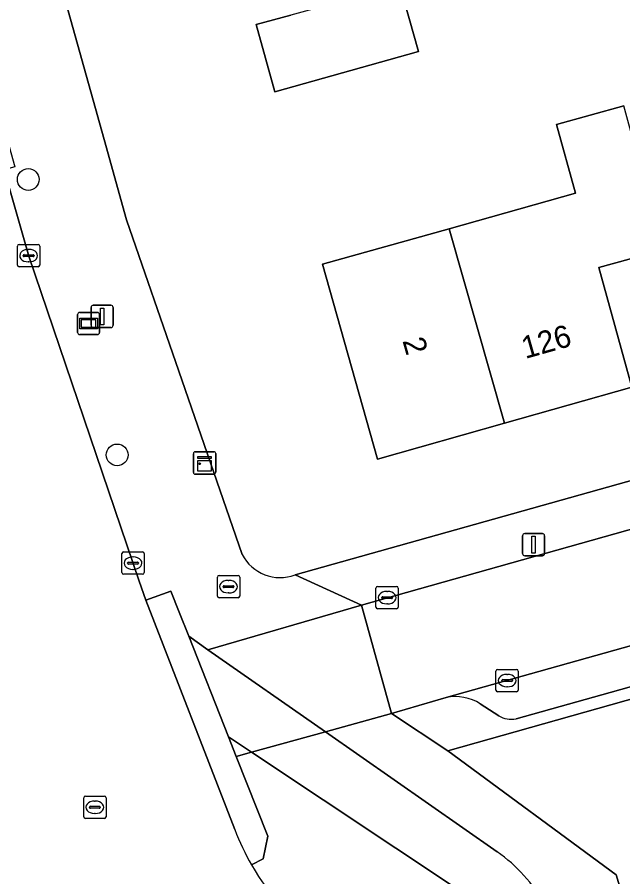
# Model space of a CAD drawing. Extents: x 159626 to 160723, y 388173 to 389416.
# Drawn here: x 160026.77 to 160053.93, y 388288.84 to 388327.38 of the extents above; entities that cross this region are included whole.
import ezdxf

# ---------------------------------------------------------------- set-up
doc = ezdxf.new("R2010")
doc.units = 0
for name, color, linetype in [('IMGEO_Boom', 7, 'Continuous'), ('IMGEO_Brandkraan', 7, 'Continuous'), ('IMGEO_Erf', 7, 'Continuous'), ('IMGEO_Fietspad_open', 7, 'Continuous'), ('IMGEO_Groenvoorziening', 7, 'Continuous'), ('IMGEO_Informatiebord', 7, 'Continuous'), ('IMGEO_Kast', 7, 'Continuous'), ('IMGEO_Kolk', 7, 'Continuous'), ('IMGEO_Lichtmast', 7, 'Continuous'), ('IMGEO_Muur', 7, 'Continuous'), ('IMGEO_Pand', 7, 'Continuous'), ('IMGEO_Pand_nummerreeks', 7, 'Continuous'), ('IMGEO_Parkeervlak_open', 7, 'Continuous'), ('IMGEO_Rijbaan_lokaal_gesloten', 7, 'Continuous'), ('IMGEO_Rijbaan_lokaal_open', 7, 'Continuous'), ('IMGEO_Rioolput', 7, 'Continuous'), ('IMGEO_Verkeerseiland_open', 7, 'Continuous'), ('IMGEO_Voetpad_open', 7, 'Continuous')]:
    doc.layers.add(name, color=color, linetype=linetype)

msp = doc.modelspace()

# ---------------------------------------------------------------- linework, layer by layer
at = {"layer": 'IMGEO_Boom'}
for centre in [(160027.263, 388320.109), (160031.247, 388307.757)]:
    msp.add_circle(centre, 0.489, dxfattribs=at)
at = {"layer": 'IMGEO_Brandkraan'}
for p, q in [((160035.743, 388301.426), (160035.743, 388302.278)), ((160035.818, 388302.352), (160036.67, 388302.352)), ((160036.744, 388302.278), (160036.744, 388301.426)), ((160036.002, 388301.846), (160036.002, 388301.858)), ((160036.045, 388301.895), (160036.443, 388301.895)), ((160036.231, 388302.132), (160036.256, 388302.132)), ((160036.486, 388301.858), (160036.486, 388301.846)), ((160036.44, 388301.809), (160036.042, 388301.809)), ((160036.254, 388301.572), (160036.229, 388301.572)), ((160036.67, 388301.352), (160035.818, 388301.352))]:
    msp.add_line(p, q, dxfattribs=at)
for points in [[(160035.743, 388301.426), (160035.743, 388302.278)], [(160035.818, 388302.352), (160036.67, 388302.352)], [(160036.744, 388302.278), (160036.744, 388301.426)], [(160036.67, 388301.352), (160035.818, 388301.352)]]:
    msp.add_lwpolyline(points, dxfattribs=at)
for centre, radius, start, end in [((160035.82, 388302.276), 0.0765, 91.552, 178.448), ((160035.82, 388302.276), 0.0765, 91.552, 178.448), ((160036.668, 388302.276), 0.0765, 1.552, 88.448), ((160036.668, 388302.276), 0.0765, 1.552, 88.448), ((160036.042, 388301.855), 0.0403, 85.8775, 175.7526), ((160036.039, 388301.845), 0.0366, 178.938, 274.7102), ((160036.443, 388301.852), 0.043, 264.8664, 352.4533), ((160036.447, 388301.857), 0.0386, 1.7309, 96.639), ((160035.82, 388301.428), 0.0765, 181.552, 268.448), ((160035.82, 388301.428), 0.0765, 181.552, 268.448), ((160036.668, 388301.428), 0.0765, 271.552, 358.448), ((160036.668, 388301.428), 0.0765, 271.552, 358.448)]:
    msp.add_arc(centre, radius, start, end, dxfattribs=at)
for centre, major_axis, ratio, start_param, end_param in [((160036.23, 388301.852), (-0.387, 0.002), 0.722429, 4.712389, 7.853982), ((160036.255, 388301.852), (-0.39, 0.002), 0.717154, 1.570796, 4.712389)]:
    msp.add_ellipse(centre, major_axis=major_axis, ratio=ratio, start_param=start_param, end_param=end_param, dxfattribs=at)
at = {"layer": 'IMGEO_Erf'}
for points in [[(160065.737, 388357.839), (160068.821, 388358.703), (160067.258, 388364.278), (160065.672, 388369.937), (160062.589, 388369.073), (160061.749, 388372.073), (160060.886, 388375.152), (160063.97, 388376.017), (160062.406, 388381.596), (160060.811, 388387.289), (160057.729, 388386.426), (160056.908, 388389.358), (160055.27, 388395.203), (160052.188, 388394.339), (160051.374, 388397.24), (160039.731, 388394.019), (160038.102, 388399.961), (160014.614, 388386.787), (160012.651, 388386.243), (160030.665, 388321.896), (160031.671, 388318.304), (160034.012, 388311.518), (160036.849, 388303.296)], [(160043.934, 388328.825), (160044.769, 388325.844), (160038.317, 388324.038), (160037.477, 388327.05), (160039.034, 388327.478)], [(160055.733, 388316.955), (160052.856, 388316.157), (160054.33, 388310.792), (160048.625, 388309.176), (160042.922, 388307.561), (160040.457, 388316.304), (160046.135, 388317.896), (160051.813, 388319.487), (160050.949, 388322.566), (160053.969, 388323.413)], [(160039.23, 388302.377), (160091.966, 388317.174)]]:
    msp.add_lwpolyline(points, dxfattribs=at)
msp.add_arc((160038.563, 388304.192), 1.934, 207.5977, 290.1919, dxfattribs=at)
at = {"layer": 'IMGEO_Fietspad_open'}
msp.add_lwpolyline([(160035.321, 388299.02), (160034.457, 388299.624), (160036.245, 388295.111), (160037.282, 388294.423), (160040.586, 388295.343)], close=True, dxfattribs=at)
for points in [[(160040.586, 388295.343), (160037.282, 388294.423), (160046.969, 388287.994)], [(160048.297, 388289.956), (160040.586, 388295.343)]]:
    msp.add_lwpolyline(points, dxfattribs=at)
msp.add_arc((160044.428, 388284.351), 6.811, 28.4759, 55.3857, dxfattribs=at)
at = {"layer": 'IMGEO_Groenvoorziening'}
msp.add_lwpolyline([(160111.162, 388314.606), (160094.986, 388310.154), (160094.139, 388309.551), (160093.281, 388307.812), (160046.081, 388294.496), (160053.63, 388288.927), (160054.524, 388285.955)], dxfattribs=at)
at = {"layer": 'IMGEO_Informatiebord'}
for p, q in [((160029.474, 388313.25), (160029.474, 388314.05)), ((160029.474, 388314.05), (160029.474, 388313.25)), ((160029.574, 388314.15), (160030.364, 388314.15)), ((160030.364, 388314.15), (160029.574, 388314.15)), ((160030.464, 388314.05), (160030.464, 388313.25)), ((160030.464, 388313.25), (160030.464, 388314.05)), ((160030.364, 388313.15), (160029.574, 388313.15)), ((160029.574, 388313.15), (160030.364, 388313.15))]:
    msp.add_line(p, q, dxfattribs=at)
for points in [[(160029.575, 388313.882), (160030.363, 388313.882), (160030.363, 388313.418), (160029.575, 388313.418), (160029.575, 388313.882)], [(160029.64, 388313.817), (160029.64, 388313.483), (160030.298, 388313.483), (160030.298, 388313.817), (160029.64, 388313.817)]]:
    msp.add_lwpolyline(points, dxfattribs=at)
for centre, start, end in [((160029.574, 388314.05), 90, 180), ((160029.574, 388314.05), 90, 180), ((160030.364, 388314.05), 0, 90), ((160030.364, 388314.05), 360, 90), ((160029.574, 388313.25), 180, 270), ((160029.574, 388313.25), 180, 270), ((160030.364, 388313.25), 270, 0), ((160030.364, 388313.25), 270, 0)]:
    msp.add_arc(centre, 0.1, start, end, dxfattribs=at)
at = {"layer": 'IMGEO_Kast'}
for p, q in [((160034.67, 388306.972), (160034.67, 388307.813)), ((160034.67, 388307.813), (160034.67, 388306.972)), ((160034.745, 388307.897), (160035.586, 388307.897)), ((160035.586, 388307.897), (160034.745, 388307.897)), ((160035.67, 388307.822), (160035.67, 388306.981)), ((160035.67, 388306.981), (160035.67, 388307.822)), ((160035.595, 388306.897), (160034.754, 388306.897)), ((160034.754, 388306.897), (160035.595, 388306.897))]:
    msp.add_line(p, q, dxfattribs=at)
for points in [[(160034.865, 388307.687), (160035.465, 388307.687), (160035.465, 388307.602), (160034.865, 388307.602), (160034.865, 388307.687)], [(160034.865, 388307.512), (160035.465, 388307.512), (160035.465, 388307.023), (160034.865, 388307.023), (160034.865, 388307.512)]]:
    msp.add_lwpolyline(points, dxfattribs=at)
msp.add_circle((160034.949, 388307.361), 0.0377, dxfattribs=at)
for centre, start, end in [((160034.748, 388307.819), 92.4484, 184.2845), ((160034.748, 388307.819), 92.4484, 184.2845), ((160035.592, 388307.819), 2.4484, 94.2845), ((160035.592, 388307.819), 2.4484, 94.2845), ((160034.748, 388306.975), 182.4484, 274.2845), ((160034.748, 388306.975), 182.4484, 274.2845), ((160035.592, 388306.975), 272.4484, 4.2845), ((160035.592, 388306.975), 272.4484, 4.2845)]:
    msp.add_arc(centre, 0.0779, start, end, dxfattribs=at)
at = {"layer": 'IMGEO_Kolk'}
for p, q in [((160026.779, 388316.267), (160026.779, 388317.119)), ((160026.854, 388317.193), (160027.706, 388317.193)), ((160027.267, 388316.973), (160027.292, 388316.973)), ((160027.78, 388317.119), (160027.78, 388316.267)), ((160027.038, 388316.687), (160027.038, 388316.699)), ((160027.476, 388316.65), (160027.078, 388316.65)), ((160027.081, 388316.736), (160027.479, 388316.736)), ((160027.522, 388316.699), (160027.522, 388316.687)), ((160027.706, 388316.193), (160026.854, 388316.193)), ((160027.29, 388316.413), (160027.265, 388316.413)), ((160031.535, 388303.406), (160032.387, 388303.406)), ((160031.46, 388302.48), (160031.46, 388303.332)), ((160031.948, 388303.186), (160031.973, 388303.186)), ((160032.461, 388303.332), (160032.461, 388302.48)), ((160031.719, 388302.9), (160031.719, 388302.912)), ((160032.157, 388302.863), (160031.759, 388302.863)), ((160031.762, 388302.949), (160032.16, 388302.949)), ((160031.971, 388302.626), (160031.946, 388302.626)), ((160032.203, 388302.912), (160032.203, 388302.9)), ((160032.387, 388302.406), (160031.535, 388302.406)), ((160042.932, 388301.859), (160043.784, 388301.859)), ((160042.857, 388300.933), (160042.857, 388301.785)), ((160043.345, 388301.639), (160043.37, 388301.639)), ((160043.858, 388301.785), (160043.858, 388300.933)), ((160043.116, 388301.353), (160043.116, 388301.365)), ((160043.554, 388301.316), (160043.156, 388301.316)), ((160043.159, 388301.402), (160043.557, 388301.402)), ((160043.368, 388301.079), (160043.343, 388301.079)), ((160043.6, 388301.365), (160043.6, 388301.353)), ((160043.784, 388300.859), (160042.932, 388300.859)), ((160048.238, 388297.214), (160048.238, 388298.066)), ((160048.313, 388298.14), (160049.165, 388298.14)), ((160049.239, 388298.066), (160049.239, 388297.214)), ((160048.497, 388297.634), (160048.497, 388297.646)), ((160048.54, 388297.683), (160048.938, 388297.683)), ((160048.726, 388297.92), (160048.751, 388297.92)), ((160048.981, 388297.646), (160048.981, 388297.634)), ((160048.935, 388297.597), (160048.537, 388297.597)), ((160048.749, 388297.36), (160048.724, 388297.36)), ((160049.165, 388297.14), (160048.313, 388297.14))]:
    msp.add_line(p, q, dxfattribs=at)
for points in [[(160026.779, 388316.267), (160026.779, 388317.119)], [(160026.854, 388317.193), (160027.706, 388317.193)], [(160027.78, 388317.119), (160027.78, 388316.267)], [(160027.706, 388316.193), (160026.854, 388316.193)], [(160031.535, 388303.406), (160032.387, 388303.406)], [(160031.46, 388302.48), (160031.46, 388303.332)], [(160032.461, 388303.332), (160032.461, 388302.48)], [(160032.387, 388302.406), (160031.535, 388302.406)], [(160042.932, 388301.859), (160043.784, 388301.859)], [(160042.857, 388300.933), (160042.857, 388301.785)], [(160043.858, 388301.785), (160043.858, 388300.933)], [(160043.784, 388300.859), (160042.932, 388300.859)], [(160048.238, 388297.214), (160048.238, 388298.066)], [(160048.313, 388298.14), (160049.165, 388298.14)], [(160049.239, 388298.066), (160049.239, 388297.214)], [(160049.165, 388297.14), (160048.313, 388297.14)]]:
    msp.add_lwpolyline(points, dxfattribs=at)
for centre, radius, start, end in [((160026.856, 388317.117), 0.0765, 91.552, 178.448), ((160026.856, 388317.117), 0.0765, 91.552, 178.448), ((160027.704, 388317.117), 0.0765, 1.552, 88.448), ((160027.704, 388317.117), 0.0765, 1.552, 88.448), ((160027.078, 388316.696), 0.0403, 85.8775, 175.7526), ((160027.075, 388316.686), 0.0366, 178.938, 274.7102), ((160027.479, 388316.693), 0.043, 264.8664, 352.4533), ((160027.483, 388316.698), 0.0386, 1.7309, 96.639), ((160026.856, 388316.269), 0.0765, 181.552, 268.448), ((160026.856, 388316.269), 0.0765, 181.552, 268.448), ((160027.704, 388316.269), 0.0765, 271.552, 358.448), ((160027.704, 388316.269), 0.0765, 271.552, 358.448), ((160031.537, 388303.33), 0.0765, 91.552, 178.448), ((160031.537, 388303.33), 0.0765, 91.552, 178.448), ((160032.385, 388303.33), 0.0765, 1.552, 88.448), ((160032.385, 388303.33), 0.0765, 1.552, 88.448), ((160031.759, 388302.909), 0.0403, 85.8775, 175.7526), ((160031.756, 388302.899), 0.0366, 178.938, 274.7102), ((160032.16, 388302.906), 0.043, 264.8664, 352.4533), ((160032.164, 388302.911), 0.0386, 1.7309, 96.639), ((160031.537, 388302.482), 0.0765, 181.552, 268.448), ((160031.537, 388302.482), 0.0765, 181.552, 268.448), ((160032.385, 388302.482), 0.0765, 271.552, 358.448), ((160032.385, 388302.482), 0.0765, 271.552, 358.448), ((160042.934, 388301.783), 0.0765, 91.552, 178.448), ((160042.934, 388301.783), 0.0765, 91.552, 178.448), ((160043.782, 388301.783), 0.0765, 1.552, 88.448), ((160043.782, 388301.783), 0.0765, 1.552, 88.448), ((160043.156, 388301.362), 0.0403, 85.8775, 175.7526), ((160043.153, 388301.352), 0.0366, 178.938, 274.7102), ((160043.557, 388301.359), 0.043, 264.8664, 352.4533), ((160043.561, 388301.364), 0.0386, 1.7309, 96.639), ((160042.934, 388300.935), 0.0765, 181.552, 268.448), ((160042.934, 388300.935), 0.0765, 181.552, 268.448), ((160043.782, 388300.935), 0.0765, 271.552, 358.448), ((160043.782, 388300.935), 0.0765, 271.552, 358.448), ((160048.315, 388298.064), 0.0765, 91.552, 178.448), ((160048.315, 388298.064), 0.0765, 91.552, 178.448), ((160049.163, 388298.064), 0.0765, 1.552, 88.448), ((160049.163, 388298.064), 0.0765, 1.552, 88.448), ((160048.537, 388297.643), 0.0403, 85.8775, 175.7526), ((160048.534, 388297.633), 0.0366, 178.938, 274.7102), ((160048.938, 388297.64), 0.043, 264.8664, 352.4533), ((160048.942, 388297.645), 0.0386, 1.7309, 96.639), ((160048.315, 388297.216), 0.0765, 181.552, 268.448), ((160048.315, 388297.216), 0.0765, 181.552, 268.448), ((160049.163, 388297.216), 0.0765, 271.552, 358.448), ((160049.163, 388297.216), 0.0765, 271.552, 358.448)]:
    msp.add_arc(centre, radius, start, end, dxfattribs=at)
for centre, major_axis, ratio, start_param, end_param in [((160027.266, 388316.693), (-0.387, 0.002), 0.722429, 4.712389, 7.853982), ((160027.291, 388316.693), (-0.39, 0.002), 0.717154, 1.570796, 4.712389), ((160031.947, 388302.906), (-0.387, 0.002), 0.722429, 4.712389, 7.853982), ((160031.972, 388302.906), (-0.39, 0.002), 0.717154, 1.570796, 4.712389), ((160043.344, 388301.359), (-0.387, 0.002), 0.722429, 4.712389, 7.853982), ((160043.369, 388301.359), (-0.39, 0.002), 0.717154, 1.570796, 4.712389), ((160048.725, 388297.64), (-0.387, 0.002), 0.722429, 4.712389, 7.853982), ((160048.75, 388297.64), (-0.39, 0.002), 0.717154, 1.570796, 4.712389)]:
    msp.add_ellipse(centre, major_axis=major_axis, ratio=ratio, start_param=start_param, end_param=end_param, dxfattribs=at)
at = {"layer": 'IMGEO_Lichtmast'}
for p, q in [((160030.08, 388313.568), (160030.08, 388314.368)), ((160030.08, 388314.368), (160030.08, 388313.568)), ((160030.18, 388314.468), (160030.97, 388314.468)), ((160030.97, 388314.468), (160030.18, 388314.468)), ((160031.07, 388314.368), (160031.07, 388313.568)), ((160031.07, 388313.568), (160031.07, 388314.368)), ((160030.97, 388313.468), (160030.18, 388313.468)), ((160030.18, 388313.468), (160030.97, 388313.468)), ((160049.531, 388304.233), (160050.321, 388304.233)), ((160050.321, 388304.233), (160049.531, 388304.233)), ((160049.431, 388303.333), (160049.431, 388304.133)), ((160049.431, 388304.133), (160049.431, 388303.333)), ((160050.421, 388304.133), (160050.421, 388303.333)), ((160050.421, 388303.333), (160050.421, 388304.133)), ((160050.321, 388303.233), (160049.531, 388303.233)), ((160049.531, 388303.233), (160050.321, 388303.233))]:
    msp.add_line(p, q, dxfattribs=at)
for points in [[(160030.5, 388314.343), (160030.65, 388314.343), (160030.65, 388313.593), (160030.5, 388313.593), (160030.5, 388314.343)], [(160049.851, 388304.108), (160050.001, 388304.108), (160050.001, 388303.358), (160049.851, 388303.358), (160049.851, 388304.108)]]:
    msp.add_lwpolyline(points, dxfattribs=at)
for centre, start, end in [((160030.18, 388314.368), 90, 180), ((160030.18, 388314.368), 90, 180), ((160030.97, 388314.368), 0, 90), ((160030.97, 388314.368), 360, 90), ((160030.18, 388313.568), 180, 270), ((160030.18, 388313.568), 180, 270), ((160030.97, 388313.568), 270, 0), ((160030.97, 388313.568), 270, 0), ((160049.531, 388304.133), 90, 180), ((160049.531, 388304.133), 90, 180), ((160050.321, 388304.133), 0, 90), ((160050.321, 388304.133), 360, 90), ((160049.531, 388303.333), 180, 270), ((160049.531, 388303.333), 180, 270), ((160050.321, 388303.333), 270, 0), ((160050.321, 388303.333), 270, 0)]:
    msp.add_arc(centre, 0.1, start, end, dxfattribs=at)
at = {"layer": 'IMGEO_Muur'}
msp.add_lwpolyline([(160030.665, 388321.896), (160031.671, 388318.304), (160034.012, 388311.518)], dxfattribs=at)
at = {"layer": 'IMGEO_Pand'}
for points in [[(160043.934, 388328.825), (160039.034, 388327.478), (160037.477, 388327.05), (160038.317, 388324.038), (160044.769, 388325.844)], [(160048.625, 388309.176), (160054.33, 388310.792), (160052.856, 388316.157), (160055.733, 388316.955), (160053.969, 388323.413), (160050.949, 388322.566), (160051.813, 388319.487), (160046.135, 388317.896)], [(160048.625, 388309.176), (160046.135, 388317.896), (160040.457, 388316.304), (160042.922, 388307.561)]]:
    msp.add_lwpolyline(points, close=True, dxfattribs=at)
at = {"layer": 'IMGEO_Parkeervlak_open'}
for points in [[(160094.7, 388310.535), (160046.003, 388296.881)], [(160049.138, 388295.93), (160092.571, 388308.096)], [(160047.537, 388296.598), (160048.365, 388296.063)]]:
    msp.add_lwpolyline(points, dxfattribs=at)
for centre, radius, start, end in [((160046.416, 388294.819), 2.103, 57.7817, 101.3129), ((160048.918, 388296.963), 1.056, 238.4321, 282.0428)]:
    msp.add_arc(centre, radius, start, end, dxfattribs=at)
at = {"layer": 'IMGEO_Rijbaan_lokaal_gesloten'}
for points in [[(160032.543, 388301.251), (160032.232, 388302.091), (160027.287, 388316.662), (160026.183, 388320.536), (160019.347, 388319.41), (160020.694, 388314.057), (160023.709, 388300.3), (160024.04, 388298.788), (160024.077, 388298.593), (160026.043, 388289.19), (160026.077, 388288.953)], [(160036.528, 388290.956), (160032.543, 388301.251)]]:
    msp.add_lwpolyline(points, dxfattribs=at)
for centre, radius, start, end in [((160046.842, 388294.888), 11.038, 200.8688, 209.9821), ((160046.909, 388294.911), 11.107, 209.9125, 258.5931)]:
    msp.add_arc(centre, radius, start, end, dxfattribs=at)
at = {"layer": 'IMGEO_Rijbaan_lokaal_open'}
msp.add_lwpolyline([(160079.586, 388311.525), (160073.017, 388309.68), (160062.717, 388306.786), (160056.177, 388304.949), (160042.215, 388301.025), (160043.548, 388296.168), (160046.003, 388296.881), (160094.7, 388310.535), (160093.373, 388315.405)], close=True, dxfattribs=at)
at = {"layer": 'IMGEO_Rioolput'}
for p, q in [((160029.749, 388291.533), (160029.749, 388292.385)), ((160029.824, 388292.459), (160030.676, 388292.459)), ((160030.237, 388292.239), (160030.262, 388292.239)), ((160030.75, 388292.385), (160030.75, 388291.533)), ((160030.008, 388291.953), (160030.008, 388291.965)), ((160030.446, 388291.916), (160030.048, 388291.916)), ((160030.051, 388292.002), (160030.449, 388292.002)), ((160030.492, 388291.965), (160030.492, 388291.953)), ((160030.676, 388291.459), (160029.824, 388291.459)), ((160030.26, 388291.679), (160030.235, 388291.679))]:
    msp.add_line(p, q, dxfattribs=at)
for points in [[(160029.749, 388291.533), (160029.749, 388292.385)], [(160029.824, 388292.459), (160030.676, 388292.459)], [(160030.75, 388292.385), (160030.75, 388291.533)], [(160030.676, 388291.459), (160029.824, 388291.459)]]:
    msp.add_lwpolyline(points, dxfattribs=at)
for centre, radius, start, end in [((160029.826, 388292.383), 0.0765, 91.552, 178.448), ((160029.826, 388292.383), 0.0765, 91.552, 178.448), ((160030.674, 388292.383), 0.0765, 1.552, 88.448), ((160030.674, 388292.383), 0.0765, 1.552, 88.448), ((160030.048, 388291.962), 0.0403, 85.8775, 175.7526), ((160030.045, 388291.952), 0.0366, 178.938, 274.7102), ((160030.449, 388291.959), 0.043, 264.8664, 352.4533), ((160030.453, 388291.964), 0.0386, 1.7309, 96.639), ((160029.826, 388291.535), 0.0765, 181.552, 268.448), ((160029.826, 388291.535), 0.0765, 181.552, 268.448), ((160030.674, 388291.535), 0.0765, 271.552, 358.448), ((160030.674, 388291.535), 0.0765, 271.552, 358.448)]:
    msp.add_arc(centre, radius, start, end, dxfattribs=at)
for centre, major_axis, ratio, start_param, end_param in [((160030.236, 388291.959), (-0.387, 0.002), 0.722429, 4.712389, 7.853982), ((160030.261, 388291.959), (-0.39, 0.002), 0.717154, 1.570796, 4.712389)]:
    msp.add_ellipse(centre, major_axis=major_axis, ratio=ratio, start_param=start_param, end_param=end_param, dxfattribs=at)
at = {"layer": 'IMGEO_Verkeerseiland_open'}
for points in [[(160034.457, 388299.624), (160034.028, 388300.707), (160033.656, 388301.646), (160032.543, 388301.251), (160036.528, 388290.956)], [(160037.281, 388289.372), (160037.805, 388289.642), (160038.008, 388290.664), (160036.594, 388294.231), (160036.245, 388295.111), (160034.457, 388299.624)], [(160037.282, 388294.423), (160036.594, 388294.231), (160038.008, 388290.664), (160037.805, 388289.642), (160037.281, 388289.372)], [(160046.969, 388287.994), (160037.282, 388294.423)]]:
    msp.add_lwpolyline(points, dxfattribs=at)
msp.add_lwpolyline([(160036.245, 388295.111), (160036.594, 388294.231), (160037.282, 388294.423)], close=True, dxfattribs=at)
for centre, radius, start, end in [((160046.842, 388294.888), 11.038, 200.8688, 209.9821), ((160046.909, 388294.911), 11.107, 209.9125, 258.5931)]:
    msp.add_arc(centre, radius, start, end, dxfattribs=at)
at = {"layer": 'IMGEO_Voetpad_open'}
for points in [[(160036.849, 388303.296), (160034.012, 388311.518), (160031.671, 388318.304), (160030.665, 388321.896), (160012.651, 388386.243)], [(160024.305, 388327.17), (160024.816, 388327.216), (160026.661, 388320.672), (160026.183, 388320.536), (160027.287, 388316.662), (160032.232, 388302.091), (160032.543, 388301.251), (160033.656, 388301.646), (160034.028, 388300.707), (160034.457, 388299.624), (160035.321, 388299.02), (160042.215, 388301.025), (160039.23, 388302.377)], [(160091.966, 388317.174), (160039.23, 388302.377), (160042.215, 388301.025), (160056.177, 388304.949), (160056.068, 388305.379), (160062.609, 388307.206), (160062.717, 388306.786), (160073.017, 388309.68), (160072.935, 388310.1), (160079.473, 388311.926), (160079.586, 388311.525), (160093.373, 388315.405)], [(160092.571, 388308.096), (160049.138, 388295.93)], [(160046.003, 388296.881), (160043.548, 388296.168), (160046.081, 388294.496), (160093.281, 388307.812)], [(160048.365, 388296.063), (160047.537, 388296.598)], [(160046.081, 388294.496), (160043.548, 388296.168), (160040.586, 388295.343), (160048.297, 388289.956)], [(160054.524, 388285.955), (160053.63, 388288.927), (160046.081, 388294.496)]]:
    msp.add_lwpolyline(points, dxfattribs=at)
msp.add_lwpolyline([(160042.215, 388301.025), (160035.321, 388299.02), (160040.586, 388295.343), (160043.548, 388296.168)], close=True, dxfattribs=at)
for centre, radius, start, end in [((160038.563, 388304.192), 1.934, 207.5977, 290.1919), ((160046.416, 388294.819), 2.103, 57.7817, 101.3129), ((160048.918, 388296.963), 1.056, 238.4321, 282.0428), ((160044.428, 388284.351), 6.811, 28.4759, 55.3857)]:
    msp.add_arc(centre, radius, start, end, dxfattribs=at)

# ---------------------------------------------------------------- texts
at = {"layer": 'IMGEO_Pand_nummerreeks'}
for s, rotation, p in [('126', 15.8133, (160049.552, 388312.057)), ('2', 285.7453, (160044.04, 388312.883))]:
    msp.add_text(s, height=1, rotation=rotation, dxfattribs=at).set_placement(p)

doc.saveas('drawing.dxf')
